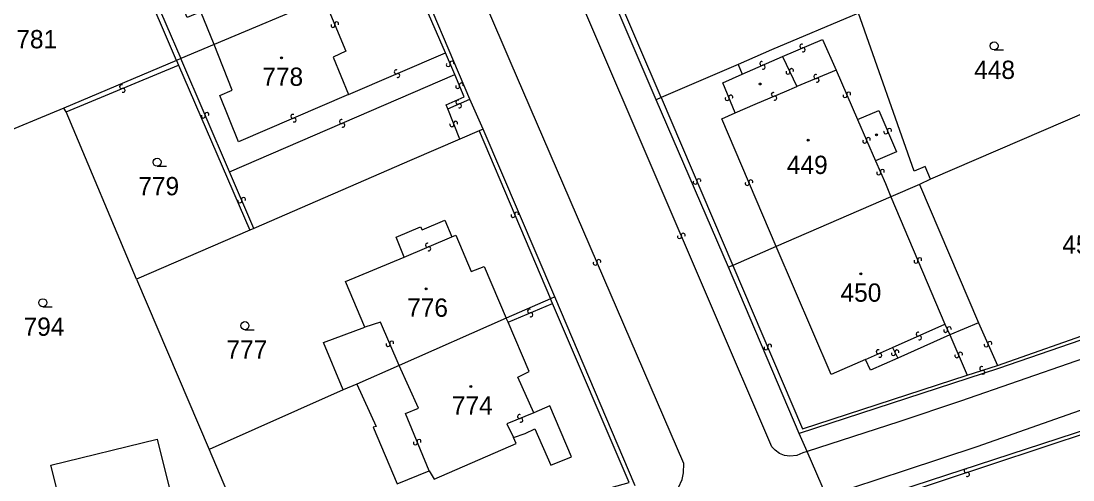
# Model space of a CAD drawing. Extents: x -600391 to -599491, y -1160176 to -1159402.
# Drawn here: x -599989.8 to -599892, y -1160069.3 to -1160026.6 of the extents above; entities that cross this region are included whole.
import ezdxf

# ---------------------------------------------------------------- set-up
doc = ezdxf.new("R2010")
doc.units = 0
for name, color, linetype in [('Level 1', 7, 'Continuous'), ('Level 13', 7, 'Continuous'), ('Level 3', 7, 'Continuous'), ('Level 4', 7, 'Continuous'), ('Level 5', 7, 'Continuous')]:
    doc.layers.add(name, color=color, linetype=linetype)

msp = doc.modelspace()

# ---------------------------------------------------------------- linework, layer by layer
at = {"layer": 'Level 1'}
for points in [[(-599975.35, -1160030.25), (-599982, -1160014.68)], [(-599930.73, -1160033.9), (-599937.42, -1160018.31)], [(-599948.07, -1160033.84), (-599953.5, -1160021.06)], [(-599961.64, -1160024.45), (-599971.83, -1160028.76)], [(-599911.93, -1160025.84), (-599920.03, -1160029.26), (-599923.13, -1160030.63)], [(-599905.23, -1160041.29), (-599905.74, -1160040.1), (-599906.76, -1160040.56), (-599911.93, -1160025.84)], [(-599971.83, -1160028.76), (-599974.95, -1160030.07)], [(-599975.35, -1160030.25), (-599985.81, -1160034.68)], [(-599974.95, -1160030.07), (-599975.35, -1160030.25)], [(-599975.35, -1160030.25), (-599975.16, -1160030.69)], [(-599975.16, -1160030.69), (-599968.53, -1160046.03)], [(-599923.13, -1160030.63), (-599930.28, -1160033.69)], [(-599930.28, -1160033.69), (-599930.73, -1160033.9)], [(-599886.45, -1160033.19), (-599905.23, -1160041.29)], [(-599985.81, -1160034.68), (-599992.58, -1160037.48)], [(-599985.61, -1160035.04), (-599985.81, -1160034.68)], [(-599946.84, -1160036.63), (-599948.07, -1160033.84)], [(-599924.02, -1160049.48), (-599930.73, -1160033.9)], [(-599979.05, -1160050.6), (-599985.61, -1160035.04)], [(-599946.84, -1160036.63), (-599947.21, -1160036.79)], [(-599940.17, -1160052.22), (-599946.84, -1160036.63)], [(-599949, -1160037.57), (-599953.45, -1160039.48), (-599968.16, -1160045.87)], [(-599947.21, -1160036.79), (-599949, -1160037.57)], [(-599905.23, -1160041.29), (-599906.25, -1160041.79)], [(-599906.25, -1160041.79), (-599908.93, -1160042.93)], [(-599906.25, -1160041.79), (-599900.76, -1160054.64)], [(-599908.93, -1160042.93), (-599919.57, -1160047.55)], [(-599954.16, -1160048.54), (-599954.92, -1160046.7), (-599952.64, -1160045.73), (-599952.5, -1160045.99), (-599950.38, -1160045.11), (-599949.73, -1160046.67)], [(-599968.53, -1160046.03), (-599979.05, -1160050.6)], [(-599968.16, -1160045.87), (-599968.53, -1160046.03)], [(-599949.73, -1160046.67), (-599949.36, -1160046.51), (-599947.94, -1160049.87), (-599946.73, -1160049.42), (-599944.7, -1160054.21)], [(-599919.57, -1160047.55), (-599923.6, -1160049.31)], [(-599911.28, -1160058.07), (-599914.47, -1160059.45), (-599919.57, -1160047.55)], [(-599957.82, -1160055.06), (-599959.62, -1160050.82), (-599954.16, -1160048.54)], [(-599923.6, -1160049.31), (-599924.02, -1160049.48)], [(-599917.43, -1160064.95), (-599924.02, -1160049.48)], [(-599979.05, -1160050.6), (-599972.3, -1160066.44)], [(-599940.17, -1160052.22), (-599940.56, -1160052.41)], [(-599932.7, -1160069.8), (-599940.17, -1160052.22)], [(-599878.65, -1160051.73), (-599889.35, -1160055.61), (-599898.91, -1160058.91), (-599917.43, -1160064.95)], [(-599940.56, -1160052.41), (-599944.7, -1160054.21)], [(-599944.7, -1160054.21), (-599954.64, -1160058.61)], [(-599944.51, -1160054.58), (-599944.7, -1160054.21)], [(-599959.84, -1160060.9), (-599961.67, -1160056.49), (-599957.82, -1160055.06)], [(-599942.13, -1160063.02), (-599943.6, -1160059.71), (-599942.56, -1160059.18), (-599944.51, -1160054.58)], [(-599900.76, -1160054.64), (-599903.43, -1160055.77)], [(-599903.43, -1160055.77), (-599908.27, -1160057.94)], [(-599908.27, -1160057.94), (-599910.82, -1160059.06), (-599911.28, -1160058.07)], [(-599954.64, -1160058.61), (-599958.56, -1160060.36)], [(-599914.24, -1160072.24), (-599890.32, -1160064.42), (-599879.7, -1160060.63), (-599875.46, -1160059.11)], [(-599959.84, -1160060.9), (-599972.3, -1160066.44)], [(-599958.56, -1160060.36), (-599959.84, -1160060.9)], [(-599958.56, -1160060.36), (-599956.78, -1160064.28), (-599957.06, -1160064.35), (-599954.81, -1160069.63), (-599951.85, -1160068.41)], [(-599944.02, -1160065.33), (-599942.93, -1160064.94), (-599942.03, -1160064.52), (-599940.54, -1160067.9), (-599938.61, -1160067.11), (-599940.63, -1160062.37), (-599942.13, -1160063.02)], [(-599916.7, -1160066.63), (-599917.43, -1160064.95)], [(-599986.23, -1160071.1), (-599987.04, -1160067.89), (-599977.13, -1160065.47), (-599974.51, -1160076.07), (-599975.5, -1160076.3)], [(-599951.85, -1160068.41), (-599951.39, -1160069.2), (-599943.77, -1160065.88), (-599944.02, -1160065.33)], [(-599972.3, -1160066.44), (-599967.02, -1160078.9)], [(-599914.89, -1160070.76), (-599916.7, -1160066.63)]]:
    msp.add_lwpolyline(points, dxfattribs=at)
at = {"layer": 'Level 13'}
for centre, start, end in [((-599960.791, -1160026.989), 149.45686, 22.04686), ((-599960.449, -1160026.852), 329.67132, 201.76931), ((-599917.21, -1160028.919), 60.28964, 292.38763), ((-599917.069, -1160029.26), 240.07518, 112.66518), ((-599950.07, -1160030.631), 150.57133, 22.66932), ((-599949.731, -1160030.488), 330.35687, 202.94687), ((-599920.933, -1160030.531), 61.25011, 293.34811), ((-599920.786, -1160030.869), 241.03565, 113.62565), ((-599954.911, -1160031.31), 60.61736, 292.71535), ((-599954.768, -1160031.649), 240.4029, 112.9929), ((-599918.487, -1160031.347), 152.15284, 24.74284), ((-599918.152, -1160031.194), 332.3673, 204.46529), ((-599915.91, -1160031.75), 59.84481, 292.43481), ((-599980.449, -1160032.689), 59.97313, 292.07113), ((-599949.2, -1160032.671), 150.40409, 22.50208), ((-599948.86, -1160032.529), 330.18963, 202.77963), ((-599915.77, -1160032.091), 240.05926, 112.15726), ((-599980.31, -1160033.03), 239.75868, 112.34868), ((-599924.141, -1160033.798), 149.70139, 21.79939), ((-599923.799, -1160033.661), 329.48693, 202.07693), ((-599919.852, -1160033.41), 60.75116, 292.84916), ((-599919.708, -1160033.749), 240.5367, 113.1267), ((-599913.179, -1160033.523), 150.65684, 23.24684), ((-599912.84, -1160033.378), 330.8713, 202.9693), ((-599949.174, -1160034.131), 61.54234, 293.64034), ((-599949.025, -1160034.468), 241.32789, 113.91789), ((-599972.85, -1160035.421), 150.70229, 22.80028), ((-599972.511, -1160035.278), 330.48783, 203.07783), ((-599964.532, -1160035.451), 60.49881, 293.08881), ((-599964.388, -1160035.79), 240.71326, 112.81126), ((-599960.012, -1160035.93), 60.75608, 292.85408), ((-599959.868, -1160036.269), 240.54163, 113.13163), ((-599949.732, -1160036.227), 149.1038, 21.20179), ((-599949.389, -1160036.093), 328.88934, 201.47934), ((-599909.05, -1160036.758), 330.82231, 202.9203), ((-599911.349, -1160037.753), 150.60785, 23.19785), ((-599911.01, -1160037.608), 330.82231, 202.9203), ((-599909.389, -1160036.903), 150.60785, 23.19785), ((-599910.049, -1160040.713), 150.68691, 23.27691), ((-599909.71, -1160040.568), 330.90136, 202.99936), ((-599927.11, -1160041.572), 150.31258, 22.90258), ((-599926.77, -1160041.429), 330.52704, 202.62504), ((-599922.28, -1160041.691), 150.54219, 22.64019), ((-599921.94, -1160041.548), 330.32773, 202.91773), ((-599969.45, -1160043.321), 150.47906, 22.57706), ((-599969.11, -1160043.179), 330.26461, 202.85461), ((-599943.71, -1160044.529), 330.43394, 202.53194), ((-599944.05, -1160044.671), 150.21949, 22.80949), ((-599928.231, -1160046.498), 330.36039, 202.95039), ((-599952.02, -1160047.429), 60.25841, 292.3564), ((-599928.57, -1160046.641), 150.57485, 22.67284), ((-599951.879, -1160047.77), 240.04395, 112.63395), ((-599936.41, -1160049.102), 150.71715, 22.81515), ((-599936.071, -1160048.958), 330.5027, 203.0927), ((-599906.58, -1160048.931), 150.18173, 22.77173), ((-599906.24, -1160048.789), 330.39618, 202.49418), ((-599942.519, -1160053.559), 59.86442, 291.96242), ((-599942.38, -1160053.9), 239.64996, 112.23996), ((-599903.827, -1160055.357), 152.30306, 24.89306), ((-599903.492, -1160055.203), 332.51752, 204.61552), ((-599906.393, -1160055.701), 61.29154, 293.38954), ((-599906.246, -1160056.039), 241.07709, 113.66709), ((-599955.67, -1160056.671), 150.65728, 22.75527), ((-599955.331, -1160056.528), 330.44282, 203.03282), ((-599920.53, -1160056.971), 150.2612, 22.8512), ((-599920.19, -1160056.829), 330.47566, 202.57365), ((-599910.093, -1160057.341), 61.33522, 293.43322), ((-599908.354, -1160057.36), 333.70582, 205.80382), ((-599900.049, -1160056.713), 150.84036, 23.43036), ((-599899.71, -1160056.567), 331.05482, 203.15282), ((-599909.946, -1160057.679), 241.12077, 113.71077), ((-599908.685, -1160057.521), 153.49136, 26.08136), ((-599902.789, -1160057.712), 150.39374, 22.98374), ((-599902.45, -1160057.569), 330.60819, 202.70619), ((-599900.474, -1160058.904), 54.94708, 287.04508), ((-599900.365, -1160059.256), 234.73263, 107.32263), ((-599943.449, -1160063.369), 59.46949, 292.05949), ((-599943.312, -1160063.711), 239.68395, 111.78194), ((-599953.131, -1160065.819), 149.93139, 22.02939), ((-599952.79, -1160065.68), 329.71694, 202.30694), ((-599901.916, -1160068.404), 55.66806, 287.76606), ((-599901.803, -1160068.755), 235.45361, 108.04361)]:
    msp.add_arc(centre, 0.184, start, end, dxfattribs=at)
at = {"layer": 'Level 3'}
for points in [[(-599916.7, -1160066.63), (-599917.11, -1160066.76), (-599917.67, -1160067), (-599918.32, -1160067.07), (-599918.8, -1160066.99), (-599919.27, -1160066.8), (-599919.69, -1160066.51), (-599919.99, -1160066.19), (-599936.81, -1160026.95), (-599950.41, -1159995.05), (-599964.44, -1159962.51), (-599964.64, -1159961.64), (-599964.57, -1159960.81), (-599964.41, -1159960.23), (-599964.11, -1159959.66), (-599963.69, -1159959.11), (-599963.03, -1159958.57)], [(-599932.07, -1160071.24), (-599930.91, -1160071.01), (-599929.76, -1160070.79), (-599929.09, -1160070.48), (-599928.67, -1160069.97), (-599928.31, -1160069.23), (-599928.2, -1160068.62), (-599928.16, -1160067.74), (-599944.31, -1160030.32), (-599957.81, -1159998.89), (-599969.74, -1159971.09), (-599971.59, -1159969.36), (-599973.79, -1159968.78), (-599975.69, -1159969.42)], [(-599930.28, -1160033.69), (-599936.98, -1160018.07)], [(-599971.83, -1160028.76), (-599973.09, -1160025.72), (-599974.36, -1160026.25), (-599977.2, -1160019.59)], [(-599979.12, -1160020.37), (-599974.95, -1160030.07)], [(-599950.34, -1160029.54), (-599953.91, -1160021.26)], [(-599961.64, -1160024.45), (-599959.61, -1160029.4), (-599960.78, -1160029.93), (-599959.35, -1160033.41)], [(-599959.35, -1160033.41), (-599969.57, -1160037.82), (-599971.32, -1160033.5), (-599970.15, -1160033), (-599971.83, -1160028.76)], [(-599918.98, -1160029.87), (-599915.29, -1160028.31), (-599914.01, -1160031.15)], [(-599959.35, -1160033.41), (-599950.34, -1160029.54)], [(-599949.47, -1160031.57), (-599950.34, -1160029.54)], [(-599922.73, -1160031.53), (-599918.98, -1160029.87)], [(-599918.98, -1160029.87), (-599917.67, -1160032.68)], [(-599985.61, -1160035.04), (-599975.16, -1160030.69)], [(-599970.4, -1160040.62), (-599974.95, -1160030.07)], [(-599923.13, -1160030.63), (-599922.73, -1160031.53)], [(-599970.4, -1160040.62), (-599949.47, -1160031.57)], [(-599950.12, -1160034.76), (-599950.27, -1160034.39), (-599948.59, -1160033.64), (-599949.47, -1160031.57)], [(-599923.39, -1160035.13), (-599924.54, -1160032.33), (-599922.73, -1160031.53)], [(-599914.01, -1160031.15), (-599917.67, -1160032.68)], [(-599914.01, -1160031.15), (-599912.01, -1160035.75)], [(-599923.39, -1160035.13), (-599921.53, -1160034.33), (-599920.74, -1160033.99), (-599918.82, -1160033.16), (-599917.67, -1160032.68)], [(-599930.28, -1160033.69), (-599923.6, -1160049.31)], [(-599950.12, -1160034.76), (-599948.07, -1160033.84)], [(-599949, -1160037.57), (-599950.12, -1160034.76)], [(-599919.57, -1160047.55), (-599924.65, -1160035.68), (-599923.39, -1160035.13)], [(-599912.01, -1160035.75), (-599910.05, -1160034.9), (-599908.38, -1160038.75), (-599910.34, -1160039.6)], [(-599912.01, -1160035.75), (-599910.34, -1160039.6)], [(-599947.21, -1160036.79), (-599940.56, -1160052.41)], [(-599840.4, -1160038.88), (-599841.34, -1160039.13), (-599864.36, -1160048.33), (-599874.5, -1160052.17), (-599880.99, -1160054.5), (-599902.43, -1160061.94), (-599908.17, -1160063.85), (-599916.7, -1160066.63)], [(-599910.34, -1160039.6), (-599909.43, -1160041.69), (-599908.93, -1160042.93)], [(-599968.16, -1160045.87), (-599970.4, -1160040.62)], [(-599914.89, -1160070.76), (-599907.55, -1160068.37), (-599900.91, -1160066.15), (-599873.39, -1160056.47), (-599862.7, -1160052.44), (-599839.71, -1160043.28), (-599838.86, -1160042.68)], [(-599908.93, -1160042.93), (-599903.89, -1160054.79)], [(-599954.16, -1160048.54), (-599949.73, -1160046.67)], [(-599923.6, -1160049.31), (-599917.12, -1160064.5), (-599901.82, -1160059.52)], [(-599899.01, -1160058.63), (-599889.49, -1160055.27), (-599878.71, -1160051.41)], [(-599967.02, -1160078.9), (-599933.24, -1160069.5), (-599940.38, -1160052.87)], [(-599944.51, -1160054.58), (-599940.38, -1160052.87)], [(-599940.38, -1160052.87), (-599940.56, -1160052.41)], [(-599954.64, -1160058.61), (-599956.37, -1160054.59), (-599957.82, -1160055.06)], [(-599908.76, -1160056.95), (-599903.89, -1160054.79)], [(-599903.89, -1160054.79), (-599903.43, -1160055.77)], [(-599900.76, -1160054.64), (-599899.01, -1160058.63)], [(-599903.43, -1160055.77), (-599901.82, -1160059.52)], [(-599911.28, -1160058.07), (-599908.76, -1160056.95)], [(-599908.76, -1160056.95), (-599908.27, -1160057.94)], [(-599951.85, -1160068.41), (-599954.06, -1160063.09), (-599952.85, -1160062.6), (-599954.64, -1160058.61)], [(-599901.82, -1160059.52), (-599899.01, -1160058.63)], [(-599903.88, -1160095.09), (-599913.57, -1160072.45), (-599890.16, -1160064.71), (-599879.57, -1160060.98), (-599875.41, -1160059.5)], [(-599942.13, -1160063.02), (-599944.64, -1160064.05), (-599944.02, -1160065.33)]]:
    msp.add_lwpolyline(points, dxfattribs=at)
at = {"layer": 'Level 5'}
for p, q in [((-599899.32, -1160029.27), (-599898.445, -1160029.27)), ((-599977.14, -1160040.09), (-599976.265, -1160040.09)), ((-599987.77, -1160053.16), (-599986.895, -1160053.16)), ((-599968.98, -1160055.29), (-599968.105, -1160055.29))]:
    msp.add_line(p, q, dxfattribs=at)
for centre, radius in [((-599899.32, -1160028.895), 0.375), ((-599965.58, -1160030.01), 0.09), ((-599965.58, -1160030.01), 0.0521), ((-599921.08, -1160032.44), 0.09), ((-599921.08, -1160032.44), 0.0521), ((-599916.6, -1160037.67), 0.09), ((-599916.6, -1160037.67), 0.0521), ((-599910.25, -1160037.17), 0.09), ((-599910.25, -1160037.17), 0.0521), ((-599977.14, -1160039.715), 0.375), ((-599911.71, -1160050.09), 0.09), ((-599911.71, -1160050.09), 0.0521), ((-599952.14, -1160051.49), 0.09), ((-599952.14, -1160051.49), 0.0521), ((-599987.77, -1160052.785), 0.375), ((-599968.98, -1160054.915), 0.375), ((-599947.98, -1160060.58), 0.09), ((-599947.98, -1160060.58), 0.0521)]:
    msp.add_circle(centre, radius, dxfattribs=at)

# ---------------------------------------------------------------- texts
at = {"layer": 'Level 4'}
for s, p in [('781', (-599990.235, -1160029.12)), ('448', (-599901.172, -1160031.97)), ('778', (-599967.361, -1160032.61)), ('449', (-599918.584, -1160040.81)), ('779', (-599978.893, -1160042.79)), ('451', (-599892.979, -1160048.23)), ('450', (-599913.599, -1160052.69)), ('776', (-599953.893, -1160054.09)), ('794', (-599989.559, -1160055.86)), ('777', (-599970.698, -1160057.99)), ('774', (-599949.733, -1160063.18))]:
    msp.add_text(s, height=1.7, dxfattribs=at).set_placement(p)

doc.saveas('drawing.dxf')
